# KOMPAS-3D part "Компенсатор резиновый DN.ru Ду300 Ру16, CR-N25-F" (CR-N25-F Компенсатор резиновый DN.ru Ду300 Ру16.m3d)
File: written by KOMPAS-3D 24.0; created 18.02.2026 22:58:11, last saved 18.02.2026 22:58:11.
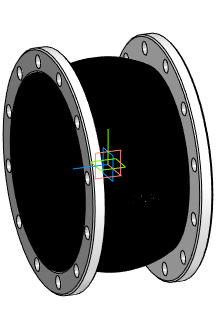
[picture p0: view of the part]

Document properties: Автор: DN.RU; Полное имя файла: D:\PROJECT CAD\DN.RU\...178(1)(ACTUALE). CR-N25-F Компенсатор резиновый DN.ru Ру10-16\DN300_PN16\CR-N25-F Компенсатор резиновый DN.ru Ду300 Ру16.m3d

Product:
- Body: Твердое тело2  | qty 1
    Масса: 102.204076
- Part/product: Компенсатор резиновый DN.ru Ду300 Ру16  | designation CR-N25-F
    Масса: 30
    Раздел спецификации: Прочие изделия
    Комментарий: D140-02402
    Примечание: D140-02402
    additional columns: Типовые

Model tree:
1. Твердое тело2  (labels: Твердое тело2)

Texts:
  CR-N25-F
